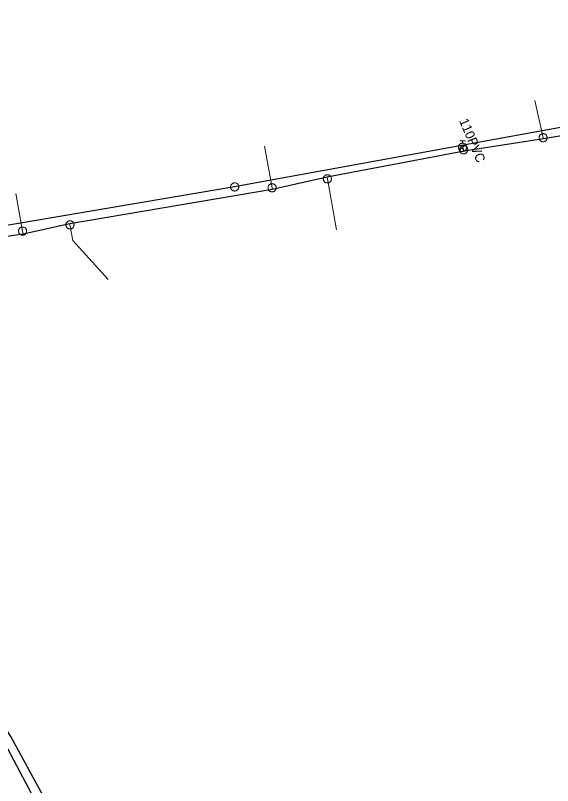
# Model space of a CAD drawing. Extents: x -741806 to -738704, y -1059275 to -1055387.
# Drawn here: x -740596.6 to -740539.1, y -1057466.5 to -1057384.1 of the extents above; entities that cross this region are included whole.
import ezdxf

# ---------------------------------------------------------------- set-up
doc = ezdxf.new("R2010")
doc.units = 0
doc.header["$LTSCALE"] = 0.4
for name, color, linetype, lineweight in [('2', 7, 'Continuous', 25), ('21', 7, 'Continuous', 13), ('3', 7, 'Continuous', 13), ('50', 7, 'Continuous', 13), ('51', 7, 'Continuous', 13), ('52', 7, 'Continuous', 25)]:
    doc.layers.add(name, color=color, linetype=linetype, lineweight=lineweight)
doc.layers.add('53', color=7, linetype='Continuous')

msp = doc.modelspace()

# ---------------------------------------------------------------- linework, layer by layer
at = {"layer": '2'}
for points in [[(-740483.87, -1057386.129), (-740524.48, -1057393.58), (-740573.109, -1057402.44), (-740629.3, -1057411.95)], [(-740551.37, -1057549.6), (-740573.489, -1057504.53), (-740597.07, -1057461.26), (-740629.3, -1057411.95)]]:
    msp.add_lwpolyline(points, dxfattribs=at)
at = {"layer": '21'}
for points in [[(-740540.033, -1057397.307), (-740540.079, -1057397.169), (-740540.978, -1057393.176)], [(-740569.092, -1057402.71), (-740569.1, -1057402.53), (-740569.914, -1057398.071)], [(-740563.186, -1057401.392), (-740563.18, -1057401.58), (-740562.188, -1057407.044)], [(-740595.761, -1057407.486), (-740595.82, -1057407.169), (-740596.548, -1057403.158)], [(-740590.765, -1057406.389), (-740590.75, -1057406.5), (-740590.456, -1057408.159), (-740586.646, -1057412.351)]]:
    msp.add_lwpolyline(points, dxfattribs=at)
at = {"layer": '3'}
msp.add_lwpolyline([(-740573.539, -1057402.518), (-740573.528, -1057402.561), (-740573.514, -1057402.604), (-740573.494, -1057402.646), (-740573.47, -1057402.685), (-740573.442, -1057402.721), (-740573.411, -1057402.755), (-740573.376, -1057402.785), (-740573.339, -1057402.811), (-740573.298, -1057402.832), (-740573.256, -1057402.85), (-740573.212, -1057402.863), (-740573.167, -1057402.872), (-740573.122, -1057402.875), (-740573.076, -1057402.875), (-740573.03, -1057402.869), (-740572.985, -1057402.859), (-740572.943, -1057402.843), (-740572.901, -1057402.824), (-740572.862, -1057402.8), (-740572.825, -1057402.772), (-740572.792, -1057402.74), (-740572.763, -1057402.706), (-740572.737, -1057402.668), (-740572.714, -1057402.628), (-740572.697, -1057402.586), (-740572.684, -1057402.542), (-740572.675, -1057402.497), (-740572.671, -1057402.451), (-740572.673, -1057402.405), (-740572.679, -1057402.36), (-740572.689, -1057402.316), (-740572.704, -1057402.273), (-740572.724, -1057402.231), (-740572.748, -1057402.191), (-740572.775, -1057402.156), (-740572.807, -1057402.122), (-740572.841, -1057402.092), (-740572.88, -1057402.066), (-740572.919, -1057402.045), (-740572.961, -1057402.027), (-740573.005, -1057402.014), (-740573.051, -1057402.005), (-740573.096, -1057402.001), (-740573.141, -1057402.002), (-740573.187, -1057402.008), (-740573.232, -1057402.018), (-740573.275, -1057402.033), (-740573.316, -1057402.053), (-740573.355, -1057402.077), (-740573.392, -1057402.105), (-740573.425, -1057402.137), (-740573.455, -1057402.171), (-740573.481, -1057402.209), (-740573.503, -1057402.249), (-740573.521, -1057402.291), (-740573.534, -1057402.336), (-740573.542, -1057402.38), (-740573.546, -1057402.426), (-740573.545, -1057402.472), (-740573.54, -1057402.517)], dxfattribs=at)
at = {"layer": '50'}
for p, q in [((-740549.007, -1057397.506), (-740548.699, -1057397.506)), ((-740548.699, -1057397.757), (-740548.699, -1057397.506)), ((-740548.392, -1057397.506), (-740548.699, -1057397.506)), ((-740548.699, -1057398.204), (-740549.016, -1057398.521)), ((-740548.699, -1057398.204), (-740548.383, -1057397.892))]:
    msp.add_line(p, q, dxfattribs=at)
msp.add_lwpolyline([(-740548.255, -1057398.208), (-740548.257, -1057398.159), (-740548.262, -1057398.113), (-740548.275, -1057398.067), (-740548.292, -1057398.024), (-740548.311, -1057397.984), (-740548.338, -1057397.943), (-740548.367, -1057397.908), (-740548.4, -1057397.873), (-740548.435, -1057397.843), (-740548.475, -1057397.819), (-740548.516, -1057397.797), (-740548.559, -1057397.778), (-740548.605, -1057397.768), (-740548.651, -1057397.76), (-740548.697, -1057397.757), (-740548.743, -1057397.76), (-740548.788, -1057397.765), (-740548.834, -1057397.778), (-740548.878, -1057397.795), (-740548.921, -1057397.816), (-740548.959, -1057397.841), (-740548.996, -1057397.87), (-740549.029, -1057397.903), (-740549.058, -1057397.938), (-740549.085, -1057397.978), (-740549.107, -1057398.019), (-740549.123, -1057398.062), (-740549.137, -1057398.108), (-740549.142, -1057398.154), (-740549.149, -1057398.2), (-740549.146, -1057398.248), (-740549.138, -1057398.294), (-740549.127, -1057398.337), (-740549.111, -1057398.383), (-740549.089, -1057398.424), (-740549.065, -1057398.464), (-740549.035, -1057398.499), (-740549.003, -1057398.534), (-740548.965, -1057398.564), (-740548.927, -1057398.588), (-740548.884, -1057398.61), (-740548.841, -1057398.626), (-740548.798, -1057398.64), (-740548.749, -1057398.648), (-740548.703, -1057398.651), (-740548.657, -1057398.648), (-740548.611, -1057398.64), (-740548.565, -1057398.629), (-740548.522, -1057398.613), (-740548.479, -1057398.591), (-740548.441, -1057398.567), (-740548.403, -1057398.537), (-740548.371, -1057398.505), (-740548.341, -1057398.47), (-740548.317, -1057398.429), (-740548.293, -1057398.389), (-740548.276, -1057398.345), (-740548.266, -1057398.3), (-740548.258, -1057398.254)], close=True, dxfattribs=at)
at = {"layer": '51'}
for points in [[(-740539.642, -1057397.169), (-740539.644, -1057397.124), (-740539.651, -1057397.079), (-740539.663, -1057397.034), (-740539.679, -1057396.992), (-740539.7, -1057396.951), (-740539.725, -1057396.912), (-740539.754, -1057396.877), (-740539.786, -1057396.844), (-740539.822, -1057396.816), (-740539.86, -1057396.791), (-740539.901, -1057396.77), (-740539.944, -1057396.753), (-740539.988, -1057396.741), (-740540.033, -1057396.734), (-740540.079, -1057396.732), (-740540.125, -1057396.734), (-740540.17, -1057396.741), (-740540.214, -1057396.753), (-740540.257, -1057396.77), (-740540.298, -1057396.791), (-740540.336, -1057396.816), (-740540.372, -1057396.844), (-740540.404, -1057396.877), (-740540.433, -1057396.912), (-740540.458, -1057396.951), (-740540.479, -1057396.992), (-740540.495, -1057397.034), (-740540.507, -1057397.079), (-740540.514, -1057397.124), (-740540.517, -1057397.17), (-740540.514, -1057397.215), (-740540.507, -1057397.26), (-740540.495, -1057397.305), (-740540.479, -1057397.347), (-740540.458, -1057397.388), (-740540.433, -1057397.427), (-740540.404, -1057397.462), (-740540.372, -1057397.495), (-740540.336, -1057397.523), (-740540.298, -1057397.548), (-740540.257, -1057397.569), (-740540.214, -1057397.586), (-740540.17, -1057397.597), (-740540.125, -1057397.605), (-740540.079, -1057397.607), (-740540.033, -1057397.605), (-740539.988, -1057397.597), (-740539.944, -1057397.586), (-740539.901, -1057397.569), (-740539.86, -1057397.548), (-740539.822, -1057397.523), (-740539.786, -1057397.495), (-740539.754, -1057397.462), (-740539.725, -1057397.427), (-740539.7, -1057397.388), (-740539.679, -1057397.347), (-740539.663, -1057397.305), (-740539.651, -1057397.26), (-740539.644, -1057397.215), (-740539.642, -1057397.17)], [(-740548.154, -1057398.462), (-740548.156, -1057398.417), (-740548.163, -1057398.372), (-740548.175, -1057398.327), (-740548.191, -1057398.285), (-740548.212, -1057398.244), (-740548.237, -1057398.205), (-740548.266, -1057398.17), (-740548.298, -1057398.137), (-740548.334, -1057398.109), (-740548.372, -1057398.084), (-740548.413, -1057398.063), (-740548.456, -1057398.046), (-740548.5, -1057398.034), (-740548.545, -1057398.027), (-740548.591, -1057398.025), (-740548.637, -1057398.027), (-740548.682, -1057398.034), (-740548.726, -1057398.046), (-740548.769, -1057398.063), (-740548.81, -1057398.084), (-740548.848, -1057398.109), (-740548.884, -1057398.137), (-740548.916, -1057398.17), (-740548.945, -1057398.205), (-740548.97, -1057398.244), (-740548.991, -1057398.285), (-740549.007, -1057398.327), (-740549.019, -1057398.372), (-740549.026, -1057398.417), (-740549.029, -1057398.463), (-740549.026, -1057398.508), (-740549.019, -1057398.553), (-740549.007, -1057398.598), (-740548.991, -1057398.64), (-740548.97, -1057398.681), (-740548.945, -1057398.72), (-740548.916, -1057398.755), (-740548.884, -1057398.788), (-740548.848, -1057398.816), (-740548.81, -1057398.841), (-740548.769, -1057398.862), (-740548.726, -1057398.879), (-740548.682, -1057398.89), (-740548.637, -1057398.898), (-740548.591, -1057398.9), (-740548.545, -1057398.898), (-740548.5, -1057398.89), (-740548.456, -1057398.879), (-740548.413, -1057398.862), (-740548.372, -1057398.841), (-740548.334, -1057398.816), (-740548.298, -1057398.788), (-740548.266, -1057398.755), (-740548.237, -1057398.72), (-740548.212, -1057398.681), (-740548.191, -1057398.64), (-740548.175, -1057398.598), (-740548.163, -1057398.553), (-740548.156, -1057398.508), (-740548.154, -1057398.463)], [(-740563.46, -1057401.244), (-740563.493, -1057401.275), (-740563.523, -1057401.309), (-740563.55, -1057401.347), (-740563.572, -1057401.387), (-740563.59, -1057401.429), (-740563.604, -1057401.473), (-740563.612, -1057401.518), (-740563.616, -1057401.564), (-740563.615, -1057401.609), (-740563.609, -1057401.654), (-740563.599, -1057401.699), (-740563.585, -1057401.743), (-740563.565, -1057401.785), (-740563.542, -1057401.824), (-740563.514, -1057401.86), (-740563.483, -1057401.894), (-740563.448, -1057401.924), (-740563.411, -1057401.95), (-740563.37, -1057401.972), (-740563.328, -1057401.99), (-740563.284, -1057402.003), (-740563.24, -1057402.013), (-740563.194, -1057402.016), (-740563.148, -1057402.016), (-740563.102, -1057402.01), (-740563.058, -1057401.999), (-740563.015, -1057401.985), (-740562.973, -1057401.965), (-740562.934, -1057401.941), (-740562.897, -1057401.914), (-740562.864, -1057401.883), (-740562.834, -1057401.849), (-740562.808, -1057401.81), (-740562.786, -1057401.771), (-740562.768, -1057401.729), (-740562.754, -1057401.685), (-740562.746, -1057401.64), (-740562.741, -1057401.594), (-740562.743, -1057401.549), (-740562.748, -1057401.503), (-740562.758, -1057401.458), (-740562.773, -1057401.415), (-740562.793, -1057401.374), (-740562.816, -1057401.334), (-740562.844, -1057401.298), (-740562.875, -1057401.264), (-740562.91, -1057401.234), (-740562.946, -1057401.208), (-740562.987, -1057401.186), (-740563.03, -1057401.168), (-740563.073, -1057401.155), (-740563.118, -1057401.145), (-740563.164, -1057401.142), (-740563.209, -1057401.142), (-740563.255, -1057401.148), (-740563.3, -1057401.158), (-740563.342, -1057401.173), (-740563.385, -1057401.193), (-740563.423, -1057401.216), (-740563.459, -1057401.244)], [(-740569.38, -1057402.194), (-740569.413, -1057402.225), (-740569.443, -1057402.259), (-740569.47, -1057402.297), (-740569.492, -1057402.337), (-740569.51, -1057402.379), (-740569.524, -1057402.423), (-740569.532, -1057402.468), (-740569.536, -1057402.514), (-740569.535, -1057402.559), (-740569.529, -1057402.604), (-740569.519, -1057402.649), (-740569.505, -1057402.693), (-740569.485, -1057402.735), (-740569.462, -1057402.774), (-740569.434, -1057402.81), (-740569.403, -1057402.844), (-740569.368, -1057402.874), (-740569.331, -1057402.9), (-740569.29, -1057402.922), (-740569.248, -1057402.94), (-740569.204, -1057402.953), (-740569.16, -1057402.963), (-740569.114, -1057402.966), (-740569.068, -1057402.966), (-740569.022, -1057402.96), (-740568.978, -1057402.949), (-740568.935, -1057402.935), (-740568.893, -1057402.915), (-740568.854, -1057402.891), (-740568.817, -1057402.864), (-740568.784, -1057402.833), (-740568.754, -1057402.799), (-740568.728, -1057402.76), (-740568.706, -1057402.721), (-740568.688, -1057402.679), (-740568.674, -1057402.635), (-740568.666, -1057402.59), (-740568.661, -1057402.544), (-740568.663, -1057402.499), (-740568.668, -1057402.453), (-740568.678, -1057402.408), (-740568.693, -1057402.365), (-740568.713, -1057402.324), (-740568.736, -1057402.284), (-740568.764, -1057402.248), (-740568.795, -1057402.214), (-740568.83, -1057402.184), (-740568.866, -1057402.158), (-740568.907, -1057402.136), (-740568.95, -1057402.118), (-740568.993, -1057402.105), (-740569.038, -1057402.095), (-740569.084, -1057402.092), (-740569.129, -1057402.092), (-740569.175, -1057402.098), (-740569.22, -1057402.108), (-740569.262, -1057402.123), (-740569.305, -1057402.143), (-740569.343, -1057402.166), (-740569.379, -1057402.194)], [(-740591.03, -1057406.164), (-740591.063, -1057406.195), (-740591.093, -1057406.229), (-740591.12, -1057406.267), (-740591.142, -1057406.307), (-740591.16, -1057406.349), (-740591.174, -1057406.393), (-740591.182, -1057406.438), (-740591.186, -1057406.484), (-740591.185, -1057406.529), (-740591.179, -1057406.574), (-740591.169, -1057406.619), (-740591.155, -1057406.663), (-740591.135, -1057406.705), (-740591.112, -1057406.744), (-740591.084, -1057406.78), (-740591.053, -1057406.814), (-740591.018, -1057406.844), (-740590.981, -1057406.87), (-740590.94, -1057406.892), (-740590.898, -1057406.91), (-740590.854, -1057406.923), (-740590.81, -1057406.933), (-740590.764, -1057406.936), (-740590.718, -1057406.936), (-740590.672, -1057406.93), (-740590.628, -1057406.919), (-740590.585, -1057406.905), (-740590.543, -1057406.885), (-740590.504, -1057406.861), (-740590.467, -1057406.834), (-740590.434, -1057406.803), (-740590.404, -1057406.769), (-740590.378, -1057406.73), (-740590.356, -1057406.691), (-740590.338, -1057406.649), (-740590.324, -1057406.605), (-740590.316, -1057406.56), (-740590.311, -1057406.514), (-740590.313, -1057406.469), (-740590.318, -1057406.423), (-740590.328, -1057406.378), (-740590.343, -1057406.335), (-740590.363, -1057406.294), (-740590.386, -1057406.254), (-740590.414, -1057406.218), (-740590.445, -1057406.184), (-740590.48, -1057406.154), (-740590.516, -1057406.128), (-740590.557, -1057406.106), (-740590.6, -1057406.088), (-740590.643, -1057406.075), (-740590.688, -1057406.065), (-740590.734, -1057406.062), (-740590.779, -1057406.062), (-740590.825, -1057406.068), (-740590.87, -1057406.078), (-740590.912, -1057406.093), (-740590.955, -1057406.113), (-740590.993, -1057406.136), (-740591.029, -1057406.164)], [(-740596.1, -1057406.833), (-740596.133, -1057406.864), (-740596.163, -1057406.898), (-740596.19, -1057406.936), (-740596.212, -1057406.976), (-740596.23, -1057407.018), (-740596.244, -1057407.062), (-740596.252, -1057407.107), (-740596.256, -1057407.153), (-740596.255, -1057407.198), (-740596.249, -1057407.243), (-740596.239, -1057407.288), (-740596.225, -1057407.332), (-740596.205, -1057407.374), (-740596.182, -1057407.413), (-740596.154, -1057407.449), (-740596.123, -1057407.483), (-740596.088, -1057407.513), (-740596.051, -1057407.539), (-740596.01, -1057407.561), (-740595.968, -1057407.579), (-740595.924, -1057407.592), (-740595.88, -1057407.602), (-740595.834, -1057407.605), (-740595.788, -1057407.605), (-740595.742, -1057407.599), (-740595.698, -1057407.588), (-740595.655, -1057407.574), (-740595.613, -1057407.554), (-740595.574, -1057407.53), (-740595.537, -1057407.503), (-740595.504, -1057407.472), (-740595.474, -1057407.438), (-740595.448, -1057407.399), (-740595.426, -1057407.36), (-740595.408, -1057407.318), (-740595.394, -1057407.274), (-740595.386, -1057407.229), (-740595.381, -1057407.183), (-740595.383, -1057407.138), (-740595.388, -1057407.092), (-740595.398, -1057407.047), (-740595.413, -1057407.004), (-740595.433, -1057406.963), (-740595.456, -1057406.923), (-740595.484, -1057406.887), (-740595.515, -1057406.853), (-740595.55, -1057406.823), (-740595.586, -1057406.797), (-740595.627, -1057406.775), (-740595.67, -1057406.757), (-740595.713, -1057406.744), (-740595.758, -1057406.734), (-740595.804, -1057406.731), (-740595.849, -1057406.731), (-740595.895, -1057406.737), (-740595.94, -1057406.747), (-740595.982, -1057406.762), (-740596.025, -1057406.782), (-740596.063, -1057406.805), (-740596.099, -1057406.833)]]:
    msp.add_lwpolyline(points, dxfattribs=at)
at = {"layer": '52'}
msp.add_line((-740548.526, -1057398.619), (-740548.699, -1057398.2), dxfattribs=at)
for points in [[(-740447.059, -1057384.081), (-740482.611, -1057386.857), (-740514.765, -1057392.747), (-740521.043, -1057394.158), (-740540.033, -1057397.307), (-740548.526, -1057398.619), (-740563.186, -1057401.392), (-740569.092, -1057402.71), (-740590.765, -1057406.389), (-740595.761, -1057407.486), (-740608.386, -1057409.341), (-740629.568, -1057413.446)], [(-740629.568, -1057413.446), (-740618.379, -1057430.067), (-740601.454, -1057456.58), (-740598.046, -1057461.412), (-740591.452, -1057473.831), (-740582.381, -1057489.777), (-740580.548, -1057493.651), (-740578.601, -1057497.165), (-740575.153, -1057503.61), (-740568.886, -1057515.331), (-740551.89, -1057550.899), (-740551.756, -1057567.162), (-740551.934, -1057571.904)]]:
    msp.add_lwpolyline(points, dxfattribs=at)

# ---------------------------------------------------------------- texts
at = {"layer": '53'}
msp.add_text('110PVC', height=1, rotation=293, dxfattribs=at).set_placement((-740549.084, -1057395.356))

doc.saveas('drawing.dxf')
